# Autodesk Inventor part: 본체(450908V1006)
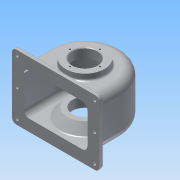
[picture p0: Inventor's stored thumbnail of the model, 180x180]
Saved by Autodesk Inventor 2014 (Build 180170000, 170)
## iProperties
Created: 2015-09
Part Number: 본체(450908V1006)
Material: 알루미늄 6061
Document SubType Name: Modeling
Designer: imci
Density: 2.71 g/cm^3
Appearance: 알루미늄 - 평지
Mass: 723.54 g
Surface Area: 889.79 cm^2
Volume: 266.989 cm^3
Author: imci
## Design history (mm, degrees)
sketch "스케치1"
  geometry: L1 (-70, 52)-(70, 52); L2 (70, 52)-(70, -52); L3 (70, -52)-(-70, -52); L4 (-70, -52)-(-70, 52); L5 (-70, 52)-(70, -52); 2 further points
  constraints: 10 end point, 2 parallel, 1 coincident, 1 horizontal, 1 midpoint, 1 perpendicular
  dimensions: "d0" = 140 distance of L1.start L1.end; "d1" = 104 distance of L1.end L2.end
extrude "돌출1" new body sketch "스케치1" distance "d2" = 7; taper "d3" = 0 deg
sketch "스케치2"
  geometry: L1 (-70, 0)-(70, 0) reference; L2 (70, 0)-(70, 7) reference; L3 (-70, 7)-(70, 7) reference; L4 (-70, 0)-(-70, 7) reference; L5 (-70, 0)-(70, 0) reference; L6 (-57, 47)-(-57, 7); L7 (57, 47)-(57, 7); A1 r 57 centre (0, 47) between (57, 47) and (-57, 47); 2 further points
  constraints: 4 end point, 2 perpendicular, 2 point on circle, 2 point on line, 2 tangent, 1 centre point, 1 midpoint, 1 vertical alignment
  dimensions: "d4" = 114 diameter of A1; "d5" = 47 distance of point (0, 0) A1.centre
extrude "돌출2" join sketch "스케치2" stored distance "d6" = 77; taper "d7" = 0 deg
sketch "스케치3"
  geometry: C1 r 31 at (0, 47); A1 r 57 centre (0, 47) between (57, 47) and (-57, 47) reference; 1 further point
  constraints: 1 centre point, 1 coincident
  dimensions: "d8" = 62 diameter of C1
extrude "돌출3" join sketch "스케치3" distance "d9" = 10; taper "d10" = 0 deg
sketch "스케치4"
  geometry: L1 (0, 0)-(0, 24); L2 (0, 0)-(24, 0); L3 (0, 0)-(0, -24); L4 (0, 0)-(-24, 0); C1 r 31 at (0, 0) reference; A1 r 24 centre (0, 0) between (0, 24) and (24, 0); 5 further points
  constraints: 8 end point, 5 coincident, 4 point on circle, 3 perpendicular, 1 centre point, 1 vertical
  dimensions: "d11" = 48 diameter of A1
hole "구멍1" sketch "스케치4" at (0, 24), (24, 0), (0, -24), (-24, 0) diameter "d12" = 2.459; stored, may be unused: countersink angle "d16" = 90 deg, drill point angle "d18" = 118 deg; dims "d13" = 6, "d14" = 4, "d15" = 2, "d17" = 8
sketch "스케치5"
  geometry: L1 (-57, 47)-(-57, 7) reference; L2 (57, 7)-(57, 47) reference; L3 (-70, 0)-(70, 0) reference; L4 (70, 0)-(70, 7) reference; L5 (-70, 7)-(70, 7) reference; L6 (-70, 0)-(-70, 7) reference; L7 (-51, 0)-(-51, 47); L8 (51, 47)-(51, 0); L9 (-51, 0)-(51, 0); A1 r 57 centre (0, 47) between (57, 47) and (-57, 47) reference; A2 r 51 centre (0, 47) between (51, 47) and (-51, 47); 1 further point
  constraints: 6 end point, 2 point on circle, 2 point on line, 1 centre point, 1 collinear
  dimensions: "d19" = 6 radial gap between concentric circles of A2 A1; "d20" = 6 distance between parallel lines of L8 L2; "d21" = 6 distance between parallel lines of L1 L7
extrude "돌출4" cut sketch "스케치5" stored distance "d22" = 67; taper "d23" = 0 deg
node "작업 평면2"
sketch "스케치9"
  geometry: C1 r 28 at (0, 47); A1 r 57 centre (0, 47) between (57, 47) and (-57, 47) reference; 1 further point
  constraints: 1 centre point, 1 coincident
  dimensions: "d31" = 56 diameter of C1
extrude "돌출6" join sketch "스케치9" stored distance "d32" = 67; taper "d33" = 40 deg
sketch "스케치12"
  geometry: L1 (75, -19.5)-(86.747, -33.5) reference; L2 (80.22, -33.5)-(84.416, -38.5); L3 (47, -38.5)-(47, 38.5) reference; L4 (47, 38.5)-(47, 38.5) reference; L5 (47, -38.5)-(47, 38.5) reference; L6 (47, -38.5)-(47, -38.5) reference; L7 (47, -38.5)-(104, -38.5) reference; L8 (47, -33.5)-(98, -33.5) reference; L9 (80.22, -33.5)-(47, -33.5); L10 (47, -38.5)-(84.416, -38.5); 1 further point
  constraints: 6 end point, 2 parallel, 2 point on line, 1 perpendicular
  dimensions: "d38" = 5 distance between parallel lines of L2 L1
revolve "회전2" sketch "스케치12" stored, may be unused: angle "d39" = 90 deg
sketch "스케치13"
  geometry: C1 r 33.22 at (0, 0) reference; C2 r 33 at (0, 0); 1 further point
  constraints: 1 centre point, 1 coincident
  dimensions: "d40" = 66 diameter of C2
extrude "돌출7" join sketch "스케치13" distance "d41" = 2; taper "d42" = 0 deg
sketch "스케치14"
  geometry: L1 (0, 0)-(0, 28); L2 (0, 0)-(-28, 0); L3 (0, 0)-(0, -28); L4 (0, 0)-(28, 0); C1 r 33 at (0, 0) reference; A1 r 28 centre (0, 0) between (0, 28) and (-28, 0); 5 further points
  constraints: 8 end point, 5 coincident, 4 point on circle, 3 perpendicular, 1 centre point, 1 vertical
  dimensions: "d43" = 56 diameter of A1
hole "구멍2" sketch "스케치14" at (0, 28), (-28, 0), (0, -28), (28, 0) diameter "d44" = 2.459; stored, may be unused: countersink angle "d48" = 90 deg, drill point angle "d50" = 118 deg; dims "d45" = 7, "d46" = 4, "d47" = 2, "d49" = 9
sketch "스케치15"
  geometry: C1 r 33 at (0, 0) reference; C2 r 20 at (0, 0); 1 further point
  constraints: 1 centre point, 1 coincident
  dimensions: "d51" = 40 diameter of C2
extrude "돌출8" cut sketch "스케치15" stored distance "d52" = 2; taper "d53" = 0 deg
node "작업 평면3"
sketch "스케치16"
  geometry: C1 r 6 at (0, 0); 1 further point
  constraints: 1 centre point, 1 coincident
  dimensions: "d55" = 12 diameter of C1
extrude "돌출9" join sketch "스케치16" stored distance "d56" = 2; taper "d57" = 10 deg
sketch "스케치17"
  geometry: C1 r 6 at (0, 0) reference; 1 further point
  constraints: 1 coincident
hole "구멍3" sketch "스케치17" at (0, 0) diameter "d58" = 4.459; stored, may be unused: countersink angle "d62" = 90 deg, drill point angle "d64" = 0 deg; dims "d59" = 7, "d60" = 4, "d61" = 2, "d63" = 9
sketch "스케치18"
  geometry: L1 (70, 52)-(-70, 52) reference; L2 (-70, 52)-(-70, -52) reference; L3 (-70, -52)-(70, -52) reference; 4 further points
  constraints: 2 vertical alignment, 1 horizontal alignment
  dimensions: "d65" = 8 distance from line of L1 point (-62, 44); "d66" = 8 distance from line of L3 point (-62, -44); "d67" = 8 distance from line of L2 point (-62, -44)
hole "구멍4" sketch "스케치18" at (-62, 44), (-62, 0), (-62, -44) diameter "d68" = 5; stored, may be unused: countersink angle "d72" = 90 deg, drill point angle "d74" = 0 deg; dims "d69" = 7, "d70" = 4, "d71" = 2, "d73" = 9
fillet "모깎기2" dims "d75" = 7
fillet "모깎기3" dims "d76" = 14
fillet "모깎기4" dims "d77" = 9
fillet "모깎기5" dims "d78" = 3
fillet "모깎기6" dims "d79" = 0.5
chamfer "모따기1" distance "d80" = 1; stored, may be unused: second distance "d81" = 2, angle "d82" = 45 deg
fillet "모깎기7" dims "d83" = 1
sketch "스케치19"
  geometry: L1 (-14, 0)-(-14, -39) reference; L2 (-20.5, -47)-(69.5, -47) reference; 2 further points
  constraints: 1 other
  dimensions: "d84" = 38.5 distance from line of L1 point (24.5, -17); "d85" = 30 distance from line of L2 point (24.5, -17)
feature "엠보싱1" sketch "스케치19" dims "d0" = 140, "d1" = 104, "d86" = 0.5, "d87" = 0
fillet "모깎기8" dims "d88" = 0.5
node "솔리드1"
mirror "대칭1"
node "투영된 루프1"
node "투영된 루프2"
node "투영된 루프3"
other parameters: "d30" = -19
